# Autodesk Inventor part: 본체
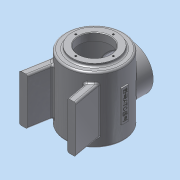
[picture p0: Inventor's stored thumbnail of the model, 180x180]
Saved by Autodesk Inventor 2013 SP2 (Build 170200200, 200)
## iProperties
Created: 2015-01
Part Number: 본체
Material: 알루미늄 6061
Document SubType Name: Modeling
Designer: dgall
Density: 2.71 g/cm^3
Mass: 1021.13 g
Surface Area: 1060.37 cm^2
Volume: 376.8 cm^3
Author: dgall
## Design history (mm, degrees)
sketch "스케치1"
  geometry: C1 r 50 at (0, 0); C2 r 38 at (0, 0); 1 further point
  constraints: 2 centre point, 1 coincident
  dimensions: "d0" = 100 diameter of C1; "d2" = 76 diameter of C2
extrude "돌출1" new body sketch "스케치1" distance "d3" = 57; taper "d4" = 0 deg
extrude "돌출2" join sketch "스케치1" distance "d5" = 62; taper "d6" = 0 deg
extrude "돌출3" join sketch "스케치1" distance "d7" = 55; taper "d8" = 0 deg
extrude "돌출4" join sketch "스케치1" distance "d9" = 60; taper "d10" = 0 deg
node "작업 평면1"
sketch "스케치2"
  geometry: L1 (-39.336, -30.865)-(-48, -80); L2 (-48, -80)-(-34, -80); L3 (-34, -80)-(-27.282, -41.901); L4 (39.336, -30.865)-(48, -80); L5 (48, -80)-(34, -80); L6 (34, -80)-(27.282, -41.901); A1 r 50 centre (0, 0) between (-39.336, -30.865) and (-27.282, -41.901) reference; 1 further point
  constraints: 12 end point, 4 point on circle, 3 equal length, 2 parallel, 1 collinear, 1 horizontal, 1 horizontal alignment
  dimensions: "d11" = 80 vertical distance of L1.end point (0, 0); "d12" = 80 deg angle of L3 L2; "d13" = 14 distance of L1.end L2.end; "d14" = 96 distance of L4.end L1.end
extrude "돌출5" join sketch "스케치2" stored distance "d15" = 80; taper "d16" = 0 deg
node "작업 평면2"
sketch "스케치3"
  geometry: C1 r 38 at (-48, -41); 1 further point
  constraints: 1 centre point, 1 coincident
  dimensions: "d18" = 76 diameter of C1
extrude "돌출6" join sketch "스케치3" stored distance "d20" = 80; taper "d21" = 0 deg
sketch "스케치4"
  geometry: L1 (-38, -60)-(38, -60) reference; L2 (38, 62)-(-38, 62) reference; L3 (0, -60)-(0, 62); L4 (0, -60)-(27, -60); L5 (27, -60)-(27, -48); L6 (27, -48)-(45, -48); L7 (45, -48)-(45, 49); L8 (45, 49)-(27, 49); L9 (27, 49)-(27, 62); L10 (27, 62)-(0, 62); 1 further point
  constraints: 16 end point, 3 perpendicular, 2 midpoint, 2 parallel, 2 point on line, 1 collinear, 1 vertical alignment
  dimensions: "d22" = 12 distance from line of L5.end L4; "d24" = 13 vertical distance of L7.end L9.end; "d25" = 54 diameter of L4.end L3; "d26" = 90 diameter of L7 L3
revolve "회전1" sketch "스케치4" stored, may be unused: angle "d27" = 90 deg
hole "구멍1" diameter "d30" = 54; stored, may be unused: countersink angle "d34" = 90 deg, drill point angle "d36" = 118 deg; dims "d28" = 10, "d29" = 10, "d31" = 6, "d32" = 4, "d33" = 2, "d35" = 8
fillet "모깎기1" dims "d37" = 3
fillet "모깎기2" dims "d38" = 3
fillet "모깎기3" dims "d39" = 3
chamfer "모따기1" distance "d40" = 1; stored, may be unused: second distance "d41" = 2, angle "d42" = 45 deg
fillet "모깎기4" dims "d43" = 3
sketch "스케치5"
  geometry: C1 r 38 at (0, 0) reference; 1 further point
  constraints: 1 vertical alignment
  dimensions: "d44" = 32 distance of point (0, 32) C1.centre
hole "구멍2" sketch "스케치5" at (0, 32) diameter "d45" = 3.242; stored, may be unused: countersink angle "d49" = 90 deg, drill point angle "d51" = 118 deg; dims "d46" = 8, "d47" = 4, "d48" = 2, "d50" = 10
sketch "스케치6"
  geometry: C1 r 38 at (0, 0) reference; 1 further point
  constraints: 1 vertical alignment
  dimensions: "d55" = 32 distance of C1.centre point (0, 32)
hole "구멍3" sketch "스케치6" at (0, 32) diameter "d56" = 3.242; stored, may be unused: countersink angle "d60" = 90 deg, drill point angle "d62" = 118 deg; dims "d57" = 8, "d58" = 4, "d59" = 2, "d61" = 10
node "작업 평면3"
sketch "스케치7"
  geometry: L1 (6, 27)-(-6, 27); L2 (-6, 27)-(-6, -27); L3 (-6, -27)-(6, -27); L4 (6, -27)-(6, 27); 3 further points
  constraints: 8 end point, 2 midpoint, 2 parallel, 1 horizontal, 1 horizontal alignment, 1 perpendicular, 1 vertical alignment
  dimensions: "d67" = 54 distance of L3.end L1.start; "d69" = 12 distance of L1.start L1.end
extrude "돌출7" join sketch "스케치7" stored distance "d70" = 80; taper "d71" = 0 deg
sketch "스케치8"
  geometry: L1 (-27, 6)-(-27, -6) reference; L2 (27, 6)-(-27, 6) reference; 4 further points
  constraints: 2 midpoint, 1 horizontal alignment, 1 vertical alignment, 1 other
feature "엠보싱1" sketch "스케치8" dims "d72" = 0.5, "d73" = 0
node "솔리드1"
pattern_circular "원형 패턴1" dims angle "d53" = 360 deg
mirror "대칭1"
pattern_circular "원형 패턴2" dims angle "d64" = 360 deg
other parameters: "d17" = -142, "d66" = 52
